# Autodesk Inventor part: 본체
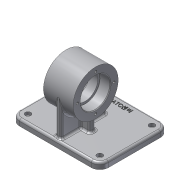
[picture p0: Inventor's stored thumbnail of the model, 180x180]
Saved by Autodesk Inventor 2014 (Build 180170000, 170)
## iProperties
Created: 2019-09
Part Number: 본체
Material: Aluminum 6061
Document SubType Name: Modeling
Designer: kh
Density: 2.71 g/cm^3
Appearance: Aluminum - Flat
Mass: 556.414 g
Surface Area: 496.445 cm^2
Volume: 205.319 cm^3
Author: kh
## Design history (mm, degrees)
sketch "Sketch1"
  geometry: L1 (-63, 49)-(63, 49); L2 (63, 49)-(63, -49); L3 (63, -49)-(-63, -49); L4 (-63, -49)-(-63, 49); L5 (-63, 49)-(63, -49); L6 (63, 49)-(-63, -49); 2 further points
  constraints: 12 end point, 2 midpoint, 2 parallel, 1 coincident, 1 horizontal, 1 perpendicular
  dimensions: "d0" = 126 distance of L1.start L1.end; "d1" = 98 distance of L1.end L2.end
extrude "Extrusion1" new body sketch "Sketch1" distance "d2" = 9; taper "d3" = 0 deg
fillet "Fillet1" dims "d4" = 12
workplane "Work Plane1"
sketch "Sketch3"
  geometry: L1 (30, 59)-(121.882, 59); L2 (30, 59)-(72, 59); L3 (72, 59)-(72, 91); L4 (72, 91)-(30, 91); L5 (30, 91)-(30, 59); L6 (51, 91)-(51, 59); L7 (114, 0)-(114, 9) reference; 1 further point
  constraints: 12 end point, 2 horizontal, 2 midpoint, 2 parallel, 1 perpendicular
  dimensions: "d8" = 59 distance from line of L1 point (51, 0); "d9" = 64 diameter of L4 L1; "d10" = 42 distance of L3.end L4.end; "d44" = 63 distance between parallel lines of L7 L6
revolve "Revolution1" sketch "Sketch3" stored, may be unused: angle "d11" = 90 deg
hole "Hole1" diameter "d14" = 36; stored, may be unused: countersink angle "d18" = 90 deg, drill point angle "d20" = 118 deg; dims "d15" = 6, "d16" = 42, "d17" = 15, "d19" = 8, "d75" = 10, "d76" = 10
mirror "Mirror1"
fillet "Fillet2" dims "d23" = 0.3
chamfer "Chamfer1" distance "d24" = 1; stored, may be unused: second distance "d25" = 2, angle "d26" = 45 deg
sketch "Sketch5" dims "d33" = 52
  geometry: C1 r 32 at (0, 0) reference; 3 further points
  constraints: 2 vertical alignment, 1 coincident, 2 other
hole "Hole2" sketch "Sketch5" at (0, -26) diameter "d34" = 3.459; stored, may be unused: countersink angle "d38" = 90 deg, drill point angle "d40" = 118 deg; dims "d35" = 8, "d36" = 42, "d37" = 2, "d39" = 10
pattern_circular "Circular Pattern1" dims angle "d42" = 360 deg
mirror "Mirror2"
sketch "Sketch4"
  geometry: L1 (-4, 19)-(4, 19); L2 (4, 19)-(4, -45); L3 (4, -45)-(-4, -45); L4 (-4, -45)-(-4, 19); L5 (-4, 19)-(4, -45); L6 (4, 19)-(-4, -45); L7 (-51, 49)-(51, 49) reference; L8 (63, 37)-(63, -37) reference; 2 further points
  constraints: 12 end point, 2 midpoint, 2 parallel, 1 horizontal, 1 perpendicular
  dimensions: "d27" = 62 distance from line of L7 point (0, -13); "d28" = 63 distance from line of L8 point (0, -13); "d29" = 64 distance of L1.end L2.end; "d30" = 8 distance of L1.start L1.end
extrude "Extrusion2" join sketch "Sketch4" stored distance "d31" = 10; taper "d32" = 0 deg
sketch "Sketch6"
  geometry: L1 (51, 0)-(51, 19.833); L2 (102, 9)-(0, 9) reference; L3 (34, 9)-(34, 21.069)
  constraints: 4 end point, 1 perpendicular, 1 point on line, 1 vertical
  dimensions: "d45" = 17 distance between parallel lines of L1 L3
feature "Rib1" sketch "Sketch6" dims "d46" = 1, "d47" = 8, "d48" = 0, "d49" = 0, "d50" = 1, "d51" = 1
sketch "Sketch7"
  geometry: L1 (102, 9)-(0, 9) reference; L2 (68, 9)-(68, 17.357); 1 further point
  constraints: 2 end point, 1 point on line, 1 vertical
  dimensions: "d52" = 17 distance from line of L2 point (51, 0)
feature "Rib2" sketch "Sketch7" dims "d53" = 1, "d54" = 8, "d55" = 0, "d56" = 0, "d57" = 1, "d58" = 1
fillet "Fillet3" dims "d59" = 3
fillet "Fillet4" dims "d60" = 3
fillet "Fillet5" dims "d61" = 3
sketch "Sketch8"
  geometry: A1 r 12 centre (-51, 37) between (-51, 49) and (-63, 37) reference; A2 r 12 centre (-51, -37) between (-63, -37) and (-51, -49) reference; A3 r 12 centre (51, -37) between (51, -49) and (63, -37) reference; A4 r 12 centre (51, 37) between (63, 37) and (51, 49) reference; 5 further points
  constraints: 4 coincident
hole "Hole3" sketch "Sketch8" at (-51, 37), (-51, -37), (51, -37), (51, 37) diameter "d62" = 4.5; stored, may be unused: countersink angle "d66" = 90 deg, drill point angle "d68" = 118 deg; dims "d63" = 8, "d64" = 8, "d65" = 4.4, "d67" = 10
sketch "Sketch9"
  geometry: L1 (-22.043, 45.573)-(22.043, 45.573); L2 (22.043, 45.573)-(22.043, 32.427); L3 (22.043, 32.427)-(-22.043, 32.427); L4 (-22.043, 32.427)-(-22.043, 45.573); L5 (-22.043, 32.427)-(22.043, 45.573); L6 (63, -37)-(63, 37) reference; L7 (51, 49)-(-51, 49) reference; L8 (0, 39)-(0, 45.573); 1 further point
  constraints: 4 end point, 2 midpoint, 1 horizontal, 2 other
  dimensions: "d73" = 63 distance between parallel lines of L6 L8; "d74" = 10 distance from line of L7 L8.start
emboss "Emboss1" sketch "Sketch9" dims "d0" = 126, "d1" = 98, "d71" = 0.5, "d72" = 0, "d76" = 10
body "Solid1"
other parameters: "d7" = -36
